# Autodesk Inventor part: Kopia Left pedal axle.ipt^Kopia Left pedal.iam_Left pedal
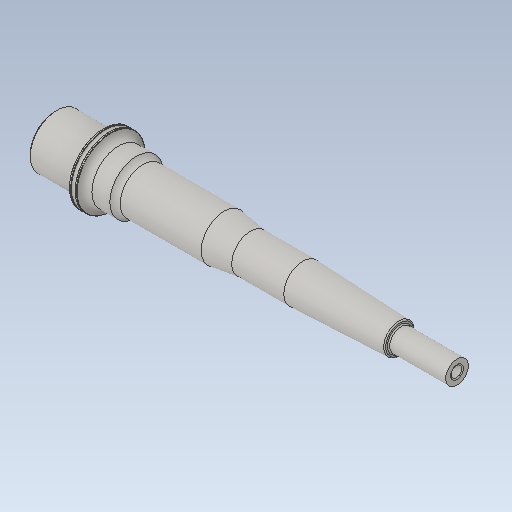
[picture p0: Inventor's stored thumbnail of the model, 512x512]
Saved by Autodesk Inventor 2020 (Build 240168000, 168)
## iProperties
Created: 2017-10
Part Number: Kopia Left pedal axle.ipt^Kopia Left pedal.iam_Left pedal
Material: solidworks materials|AISI 4130 Stal normalizowana w 870C|95
Document SubType Name: Modeling
Designer: Tomasz
Density: 7.85 g/cm^3
Appearance: 166,158,150
Sending System: SolidWorks 2017
Last Author: Tomasz
Last Saved: 2017-11-19
Author: Tomasz
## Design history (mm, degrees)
feature "Left pedal axle.ipt"
node "Bryła1"
